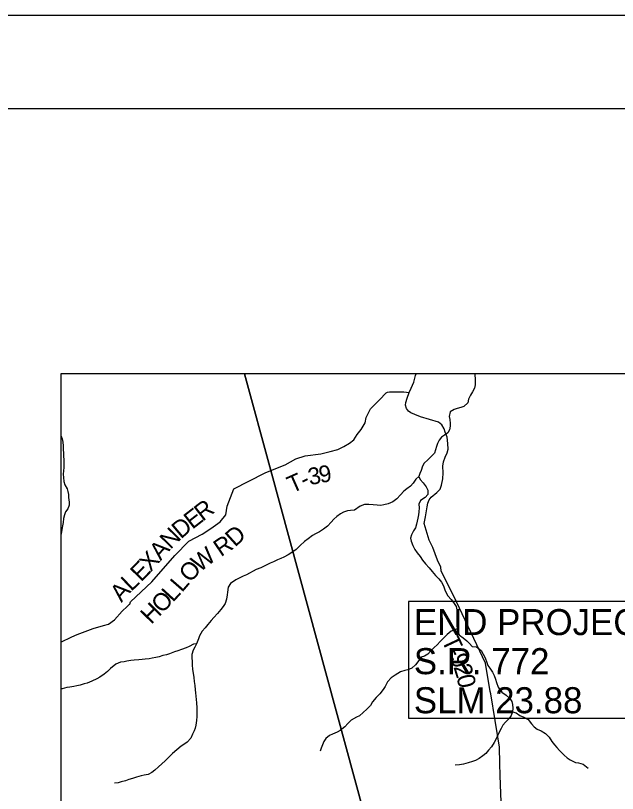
# Model space of a CAD drawing. Extents: x -139 to 835, y 0 to 440.
# Drawn here: x 62.7 to 127.4, y 356.4 to 440 of the extents above; entities that cross this region are included whole.
import ezdxf

# ---------------------------------------------------------------- set-up
doc = ezdxf.new("R2010")
doc.units = 0
for name, color, linetype in [('Default', 7, 'Continuous'), ('GM_X_County_Text', 7, 'Continuous'), ('GM_X_Minor_River', 7, 'Continuous'), ('GM_X_Township_Road', 7, 'Continuous'), ('GM_X_Township_Road_Text', 7, 'Continuous'), ('SH_Border', 7, 'Continuous'), ('SH_Cut_Line', 7, 'Continuous'), ('SH_Text', 7, 'Continuous')]:
    doc.layers.add(name, color=color, linetype=linetype)

msp = doc.modelspace()

# ---------------------------------------------------------------- linework, layer by layer
at = {"layer": 'Default'}
msp.add_lwpolyline([(121.629, 360.501), (121.629, 360.501), (121.629, 360.501), (121.629, 360.501)], close=True, dxfattribs=at)
at = {"layer": 'GM_X_County_Text'}
for points in [[(87.298, 401.486), (67.578, 401.486), (67.578, 336.518), (92.493, 334.759), (105.67, 333.828), (100.145, 354.177), (90.116, 391.109)], [(205.139, 401.486), (87.298, 401.486), (90.116, 391.109), (100.145, 354.177), (105.67, 333.828), (158.444, 330.1), (160.688, 329.921), (171.559, 329.033), (172.321, 330.669), (184.767, 357.384), (185.383, 358.364), (185.729, 359.048), (185.902, 359.821), (186.018, 360.334), (186.292, 360.95), (186.616, 361.275), (187.014, 361.689), (203.078, 396.689), (203.294, 397.153), (203.246, 397.371), (203.278, 397.973), (203.623, 399.152)]]:
    msp.add_lwpolyline(points, close=True, dxfattribs=at)
at = {"layer": 'GM_X_Minor_River'}
for points in [[(112.06, 401.486), (112.048, 401.361), (112.08, 400.902), (112.102, 400.589), (112.085, 400.287), (112.005, 399.939), (111.81, 399.531), (111.59, 399.196), (111.369, 398.752), (111.289, 398.367), (110.853, 397.962), (110.535, 397.881), (110.166, 397.74), (109.835, 397.648), (109.401, 397.387), (109.294, 396.906), (109.366, 396.568), (109.398, 396.157), (109.382, 395.856), (109.314, 395.447), (109.145, 395.135), (108.8, 394.898), (108.455, 394.685), (108.223, 394.35), (108.041, 393.99), (107.923, 393.678), (107.805, 393.33), (107.699, 392.969), (107.314, 392.551), (106.993, 392.241), (106.608, 391.884), (106.44, 391.548), (106.282, 391.104), (106.138, 390.756), (106.033, 390.443), (106.181, 390.14), (106.481, 389.763), (106.818, 389.35), (106.991, 388.974), (107.01, 388.515), (106.702, 388.205), (106.216, 387.849), (106.047, 387.477), (106.055, 387.067), (106.036, 386.633), (105.995, 386.32), (105.927, 385.983), (105.847, 385.647), (105.792, 385.31), (105.661, 384.925), (105.466, 384.602), (105.258, 384.158), (105.127, 383.834), (105.212, 383.495), (105.384, 383.035), (105.619, 382.599), (105.856, 382.258), (106.167, 381.833), (106.416, 381.444), (106.753, 381.055), (107.14, 380.616), (107.453, 380.239), (107.84, 379.813), (108.19, 379.435), (108.465, 379.083), (108.675, 378.694), (108.835, 378.259), (108.983, 377.943), (109.156, 377.628), (109.519, 377.214), (109.768, 376.898)], [(67.578, 394.846), (67.699, 394.498), (67.796, 394.123), (67.83, 393.749), (67.837, 393.363), (67.845, 392.965), (67.866, 392.615), (67.9, 392.253), (67.907, 391.794), (67.889, 391.397), (67.86, 391.06), (67.83, 390.698), (67.851, 390.324), (67.896, 389.926), (68.006, 389.563), (68.241, 389.138), (68.339, 388.824), (68.386, 388.522), (68.407, 388.172), (68.452, 387.701), (68.46, 387.364), (68.316, 386.967), (68.071, 386.644), (67.966, 386.308), (67.872, 385.923), (67.816, 385.514), (67.761, 385.153), (67.68, 384.708), (67.599, 384.287), (67.578, 384.158)], [(106.033, 390.443), (105.725, 390.157), (105.429, 389.739), (105.146, 389.416), (104.737, 389.107), (104.417, 388.858), (104.07, 388.476), (103.659, 388.058), (103.25, 387.737), (102.74, 387.502), (102.282, 387.386), (101.94, 387.342), (101.547, 387.358), (101.117, 387.411), (100.648, 387.453), (100.192, 387.434), (99.746, 387.27), (99.108, 386.843), (98.688, 386.775), (98.359, 386.755), (97.926, 386.603), (97.607, 386.437), (97.236, 386.164), (96.916, 385.854), (96.608, 385.532), (96.222, 385.103), (95.8, 384.794), (95.366, 384.497), (94.945, 384.285), (94.6, 384.096), (94.14, 383.763), (93.743, 383.454), (93.269, 383.025), (92.846, 382.584), (92.386, 382.276), (91.977, 382.027), (91.518, 381.779), (91.199, 381.626), (90.855, 381.497), (90.434, 381.284), (90.078, 381.144), (89.479, 380.837), (89.045, 380.625), (88.574, 380.437), (88.242, 380.272), (87.847, 380.071), (87.503, 379.882), (87.146, 379.717), (86.713, 379.529), (86.355, 379.328), (85.793, 378.961), (85.56, 378.541), (85.465, 378.024), (85.436, 377.711), (85.367, 377.253), (85.209, 376.797), (85.002, 376.474), (84.77, 376.151), (84.397, 375.709), (84.012, 375.291), (83.729, 374.957), (83.369, 374.551), (83.073, 374.18), (82.752, 373.822), (82.48, 373.331), (82.349, 372.995), (82.139, 372.467), (81.97, 372.083), (81.801, 371.771), (81.656, 371.315), (81.64, 371.001), (81.685, 370.531), (81.693, 370.193), (81.725, 369.698), (81.771, 369.312), (81.854, 368.829), (81.912, 368.406), (81.957, 367.972), (82.015, 367.513), (82.036, 367.187), (82.116, 366.487), (82.15, 366.125), (82.169, 365.594), (82.19, 365.244), (82.199, 364.943), (82.182, 364.642), (82.152, 364.232), (82.07, 363.727), (82.002, 363.402), (81.91, 363.09), (81.728, 362.73), (81.533, 362.334), (81.147, 361.88), (80.802, 361.631), (80.483, 361.442), (80.035, 361.073), (79.561, 360.68), (79.138, 360.251), (78.765, 359.87), (78.06, 359.226), (77.663, 358.881)], [(109.768, 376.898), (110.029, 376.461), (110.113, 376.11), (110.171, 375.663), (110.191, 375.241), (110.186, 374.831), (110.169, 374.434), (110.139, 374.084), (110.248, 373.685), (110.396, 373.382), (110.799, 373.112), (111.2, 372.782), (111.488, 372.478), (111.763, 372.173), (112.231, 372.12), (112.72, 371.729), (112.944, 371.364), (113.141, 370.952), (113.325, 370.456), (113.461, 370.141), (113.647, 369.825), (113.959, 369.424), (114.131, 369.036), (114.279, 368.649), (114.388, 368.298), (114.56, 367.802), (114.959, 367.267), (115.398, 366.936), (115.825, 366.582), (116.011, 366.254), (116.108, 365.94), (116.141, 365.529), (116.111, 365.132), (115.954, 364.748), (115.722, 364.425), (115.349, 364.031), (115.067, 363.697), (114.872, 363.373), (114.638, 362.882), (114.495, 362.57), (114.339, 362.258), (114.131, 361.851), (113.834, 361.384), (113.513, 361.014), (113.23, 360.679), (112.91, 360.43), (112.513, 360.121), (112.118, 359.92), (111.8, 359.791), (111.342, 359.663), (110.833, 359.537), (110.414, 359.457), (109.932, 359.402)], [(110.139, 374.084), (109.808, 373.931), (109.489, 373.826), (109.08, 373.469), (108.759, 373.147), (108.322, 372.694), (108.001, 372.348), (107.668, 372.062), (107.27, 371.657), (107.013, 371.334), (106.643, 371.145), (106.274, 371.017), (105.938, 370.514), (105.681, 370.192), (105.271, 369.834), (104.851, 369.67), (104.533, 369.589), (104.075, 369.438), (103.475, 369.095), (103.053, 368.786), (102.68, 368.356), (102.421, 367.865), (102.202, 367.554), (101.854, 367.099), (101.443, 366.682), (101.057, 366.216), (100.837, 365.845), (100.44, 365.439), (100.042, 365.07), (99.658, 364.725), (99.339, 364.572), (98.778, 364.252), (98.406, 363.883), (98.084, 363.537), (97.598, 363.156), (97.254, 362.979), (96.757, 362.756), (96.438, 362.59), (96.054, 362.293), (95.809, 361.946), (95.678, 361.61), (95.547, 361.25), (95.442, 360.926)], [(82.139, 372.467), (81.822, 372.41), (81.363, 372.174), (81.044, 372.021), (80.548, 371.833), (80.128, 371.693), (79.784, 371.601), (79.262, 371.377), (78.919, 371.285), (78.538, 371.205), (78.13, 371.052), (77.787, 370.996), (77.394, 370.916), (77.076, 370.859), (76.632, 370.792), (76.302, 370.771), (75.947, 370.739), (75.465, 370.708), (75.084, 370.676), (74.678, 370.596), (74.36, 370.54), (73.992, 370.471), (73.47, 370.284), (72.894, 369.808), (72.573, 369.486), (72.215, 369.213), (71.767, 368.881), (71.423, 368.679), (70.9, 368.444), (70.404, 368.245), (70.086, 368.14), (69.641, 368.012), (69.297, 367.932), (68.967, 367.887), (68.548, 367.807), (68.205, 367.751), (67.697, 367.636), (67.578, 367.612)], [(116.111, 365.132), (116.49, 365.055), (116.879, 364.738), (117.32, 364.588), (117.761, 364.318), (118.148, 363.843), (118.41, 363.539), (118.736, 363.294), (119.178, 363.108), (119.655, 362.802), (120.018, 362.412), (120.316, 361.95), (120.591, 361.61), (120.866, 361.305), (121.141, 360.976), (121.629, 360.501), (121.955, 360.22), (122.307, 359.975), (122.848, 359.716), (123.203, 359.663), (123.695, 359.537), (124.235, 359.109)], [(77.663, 358.881), (77.331, 358.62), (76.961, 358.419), (76.516, 358.327), (76.186, 358.259), (75.69, 358.119), (75.257, 357.968), (74.888, 357.863), (74.519, 357.747), (74.049, 357.619), (73.718, 357.527), (73.338, 357.483)]]:
    msp.add_lwpolyline(points, dxfattribs=at)
at = {"layer": 'GM_X_Township_Road'}
for points in [[(105.01, 399.465), (105.212, 399.944), (105.491, 400.586), (105.692, 401.296), (105.743, 401.486)], [(89.523, 390.836), (90.124, 391.092), (91.659, 391.711), (92.823, 392.329), (93.806, 392.652), (95.496, 392.891), (96.507, 393.131), (97.332, 393.346), (97.984, 393.687), (98.596, 394.028), (99.062, 394.381), (99.411, 394.946), (99.827, 395.509), (100.266, 396.218), (100.389, 396.793), (100.824, 397.731), (101.798, 398.699), (102.522, 399.437), (102.676, 399.51), (102.867, 399.533), (103.834, 399.538), (104.428, 399.533), (105.01, 399.465)], [(108.394, 380.716), (108.03, 381.437), (107.549, 382.822), (107.154, 383.604), (106.622, 385.38), (106.742, 386.106), (106.929, 387.175), (107.007, 387.596), (107.145, 387.93), (107.371, 388.237), (107.984, 388.727), (108.339, 389.103), (108.455, 389.51), (108.617, 390.181), (108.664, 390.857), (108.599, 391.559), (108.678, 392.04), (108.847, 392.531), (109.079, 393.007), (109.167, 393.391), (109.149, 393.996), (109.07, 394.662), (108.872, 395.2), (108.77, 395.577), (108.505, 396.008), (108.145, 396.273), (106.227, 396.874), (105.609, 397.122), (105.158, 397.303), (104.933, 397.488), (104.713, 397.77), (104.588, 398.125), (104.618, 398.39), (104.796, 398.874), (105.01, 399.465)], [(74.708, 376.479), (74.956, 376.717), (74.979, 376.738), (75.045, 376.957), (77.336, 379.13), (79.804, 381.954), (81.313, 383.501), (82.74, 384.236), (83.678, 384.854), (84.697, 385.589), (85.308, 386.324), (85.431, 387.252), (85.798, 388.181), (86.165, 389.109), (89.463, 390.811), (89.523, 390.836)], [(113.711, 367.342), (113.208, 370.39), (110.072, 376.958), (108.432, 380.303), (108.408, 380.688), (108.394, 380.716)], [(67.578, 372.641), (68.755, 373.213), (69.314, 373.478), (71.04, 374.089), (72.139, 374.412), (72.699, 374.559), (73.319, 375.052), (74.165, 375.961), (74.708, 376.479)], [(114.741, 359.581), (114.7, 361.357), (113.757, 367.065), (113.711, 367.342)], [(114.73, 351.757), (114.92, 354.47), (114.77, 358.303), (114.741, 359.581)]]:
    msp.add_lwpolyline(points, dxfattribs=at)
at = {"layer": 'SH_Border'}
msp.add_lwpolyline([(30, 430), (670, 430), (670, 10), (30, 10)], close=True, dxfattribs=at)
at = {"layer": 'SH_Cut_Line'}
for points in [[(0, 0), (680, 0), (680, 440), (0, 440)], [(295.458, 319.381), (295.458, 401.486), (67.578, 401.486), (67.578, 336.518), (92.493, 334.759), (105.67, 333.828), (158.444, 330.1), (160.688, 329.921), (171.559, 329.033), (177.155, 328.576), (194.287, 327.176), (207.436, 326.102), (228.151, 324.569), (267.909, 321.538)]]:
    msp.add_lwpolyline(points, close=True, dxfattribs=at)
at = {"layer": 'SH_Text'}
msp.add_lwpolyline([(131.202, 377.001), (104.926, 377.001), (104.926, 364.463), (131.202, 364.463)], close=True, dxfattribs=at)

# ---------------------------------------------------------------- texts
at = {"layer": 'GM_X_Township_Road_Text'}
for s, height, rotation, p in [('3', 1.812, 10.88499, (94.312, 389.507)), ('9', 1.811, 10.19815, (95.455, 389.727)), ('T', 1.834, 23.99122, (92.397, 388.615)), ('-', 1.837, 25.6262, (93.742, 389.214)), ('R', 1.862, 37.65873, (82.802, 385.566)), ('E', 1.862, 37.76005, (81.699, 384.712)), ('D', 1.867, 40.06281, (80.461, 383.671)), ('N', 1.876, 45.58887, (79.356, 382.539)), ('D', 1.87, 42.16338, (86.278, 382.8)), ('R', 1.854, 33.91155, (84.769, 381.76)), ('A', 1.881, 48.38649, (78.292, 381.341)), ('W', 1.863, 37.98463, (82.493, 380.103)), ('X', 1.881, 48.90185, (77.227, 380.12)), ('E', 1.877, 45.95412, (76.195, 379.048)), ('O', 1.88, 48.19501, (81.473, 378.95)), ('L', 1.873, 43.57398, (75.13, 378.033)), ('A', 1.881, 48.47369, (74.081, 376.846)), ('L', 1.882, 49.02495, (80.572, 377.913)), ('L', 1.879, 47.46526, (79.601, 376.853)), ('O', 1.877, 45.98432, (78.433, 375.644)), ('H', 1.876, 45.38084, (77.274, 374.469)), ('T', 1.898, 295.07359, (108.429, 372.865)), ('9', 1.899, 292.63286, (109.315, 370.971)), ('-', 1.898, 295.07359, (109.006, 371.631)), ('2', 1.901, 287.72934, (109.733, 369.974)), ('0', 1.903, 282.80101, (110.063, 368.947))]:
    msp.add_text(s, height=height, rotation=rotation, dxfattribs=at).set_placement(p)
at = {"layer": 'SH_Text'}
for s, p in [('END PROJECT', (105.496, 373.395)), ('S.R. 772          ', (105.496, 369.195)), ('SLM 23.88      ', (105.496, 364.995))]:
    msp.add_text(s, height=2.79999, dxfattribs=at).set_placement(p)

doc.saveas('drawing.dxf')
